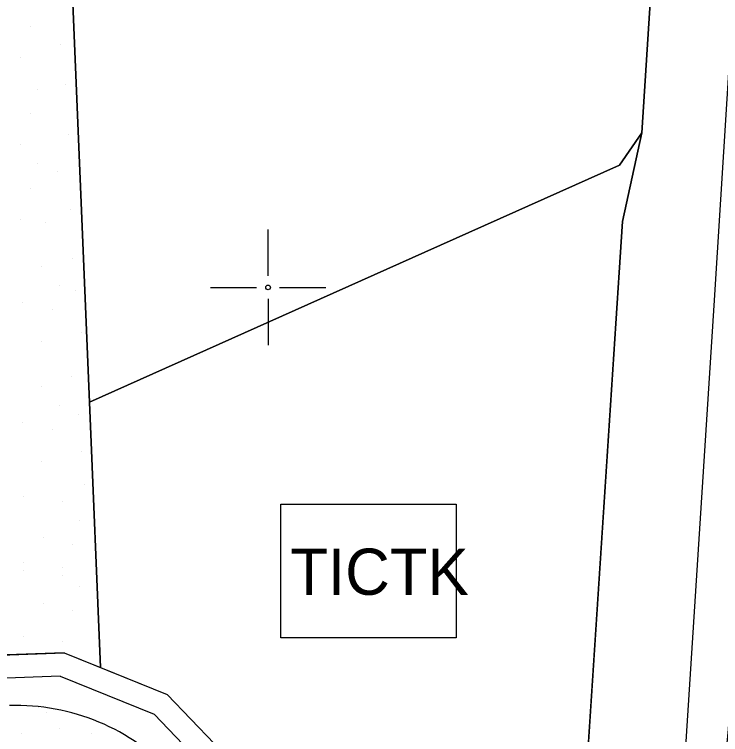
# Model space of a CAD drawing. Extents: x 419109 to 421295, y 4452223 to 4457798.
# Drawn here: x 419945.1 to 420098, y 4453403.2 to 4453559.1 of the extents above; entities that cross this region are included whole.
import ezdxf

# ---------------------------------------------------------------- set-up
doc = ezdxf.new("R2010")
doc.units = 0
for name, color, linetype in [('ADA', 7, 'Continuous'), ('ADAKENARI', 7, 'Continuous'), ('Default', 7, 'Continuous'), ('KALDIRIM', 7, 'Continuous'), ('LJ_SEMBOL', 7, 'Continuous'), ('PAFTALAMA', 7, 'Continuous'), ('PL_AYA_PARK_DINLENME', 7, 'Continuous'), ('PL_TURZM', 7, 'Continuous'), ('RAYLI_TOPLU_TAŞIMA_HATTI', 7, 'Continuous'), ('TR_PARKALANI', 7, 'Continuous'), ('TR_TİC_TURIZM_K', 7, 'Continuous'), ('TR_TİCT', 7, 'Continuous')]:
    doc.layers.add(name, color=color, linetype=linetype)

# ---------------------------------------------------------------- blocks, each defined once
blk = doc.blocks.new('POINT_DISPLAY')
at = {"layer": 'Default'}
blk.add_line((0, 0), (0, 0), dxfattribs=at)

msp = doc.modelspace()

# ---------------------------------------------------------------- linework, layer by layer
at = {"layer": 'ADA'}
msp.add_line((419963.74, 4453417.74), (419952.2, 4453694.42), dxfattribs=at)
at = {"layer": 'ADAKENARI'}
for p, q in [((420084.07, 4453583.1), (420080.95, 4453533.45)), ((420076.07, 4453526.42), (420080.95, 4453533.45)), ((420080.95, 4453533.45), (420076.74, 4453514.23)), ((420076.07, 4453526.42), (420033.97, 4453507.61)), ((420076.74, 4453514.23), (420065.91, 4453348.58)), ((420033.97, 4453507.61), (419961.35, 4453475.15)), ((419955.88, 4453420.93), (419903.4, 4453419.08)), ((419955.88, 4453420.93), (419978.18, 4453411.89)), ((419978.18, 4453411.89), (419988.41, 4453401.25))]:
    msp.add_line(p, q, dxfattribs=at)
msp.add_arc((419945.6, 4453363.53), 46, 42.5151, 92.0182, dxfattribs=at)
at = {"layer": 'KALDIRIM'}
for p, q in [((420100.06, 4453552.29), (420096.48, 4453496.11)), ((420096.48, 4453496.11), (420075.56, 4453167.83)), ((419954.99, 4453415.89), (419903.57, 4453414.08)), ((419954.99, 4453415.89), (419975.31, 4453407.66)), ((419975.31, 4453407.66), (419984.63, 4453397.97))]:
    msp.add_line(p, q, dxfattribs=at)
at = {"layer": 'LJ_SEMBOL'}
msp.add_lwpolyline([(420002.78, 4453453.1), (420040.72, 4453453.1), (420040.72, 4453424.16), (420002.78, 4453424.16)], close=True, dxfattribs=at)
at = {"layer": 'PAFTALAMA'}
for p, q in [((420000, 4453502.5), (420000, 4453512.5)), ((419987.5, 4453500), (419997.5, 4453500)), ((420002.5, 4453500), (420012.5, 4453500)), ((420000, 4453497.5), (420000, 4453487.5))]:
    msp.add_line(p, q, dxfattribs=at)
msp.add_circle((420000, 4453500), 0.5, dxfattribs=at)
at = {"layer": 'PL_AYA_PARK_DINLENME'}
msp.add_lwpolyline([(419961.35, 4453475.15), (419952.2, 4453694.42), (419939.23, 4453693.51), (419936.24, 4453693.29), (419939.48, 4453615.5), (419914.93, 4453613.25), (419917.11, 4453561.14), (419919.26, 4453509.4), (419938.37, 4453510.08), (419942.11, 4453420.44), (419955.88, 4453420.93), (419963.74, 4453417.74), (419961.35, 4453475.15)], dxfattribs=at)
msp.add_arc((419945.6, 4453363.53), 46, 42.5151, 92.0182, dxfattribs=at)
at = {"layer": 'PL_TURZM'}
for points in [[(419952.2, 4453694.42), (419961.35, 4453475.15), (420033.97, 4453507.61), (420076.07, 4453526.42), (420080.95, 4453533.45), (420084.07, 4453583.1)], [(419961.35, 4453475.15), (419963.74, 4453417.74), (419978.18, 4453411.89), (419988.41, 4453401.25), (419997.92, 4453389.08), (420007.85, 4453361.47), (420006.28, 4453340.53), (420065.42, 4453341.09), (420065.91, 4453348.58), (420076.74, 4453514.23), (420080.95, 4453533.45), (420076.07, 4453526.42), (420033.97, 4453507.61), (419961.35, 4453475.15)]]:
    msp.add_lwpolyline(points, dxfattribs=at)
at = {"layer": 'RAYLI_TOPLU_TAŞIMA_HATTI'}
msp.add_arc((425082.72, 4452994.01), 5000, 175.25584, 176.39423, dxfattribs=at)
at = {"layer": 'TR_TİC_TURIZM_K'}
for points in [[(420065.42, 4453341.09), (420065.91, 4453348.58), (420076.74, 4453514.23), (420080.95, 4453533.45), (420076.07, 4453526.42), (420033.97, 4453507.61), (419961.35, 4453475.15), (419963.74, 4453417.74), (419978.18, 4453411.89), (419988.41, 4453401.25), (419997.92, 4453389.08), (420007.85, 4453361.47), (420006.28, 4453340.53), (420065.42, 4453341.09)], [(420002.78, 4453424.16), (420002.78, 4453453.1), (420040.72, 4453453.1), (420040.72, 4453424.16), (420002.78, 4453424.16)]]:
    msp.add_lwpolyline(points, dxfattribs=at)
at = {"layer": 'TR_TİCT'}
msp.add_lwpolyline([(419952.2, 4453694.42), (419961.35, 4453475.15), (420033.97, 4453507.61), (420076.07, 4453526.42), (420080.95, 4453533.45), (420084.07, 4453583.1)], dxfattribs=at)

# ---------------------------------------------------------------- block references
at = {"layer": 'TR_PARKALANI', "xscale": 0.1, "yscale": 0.10000000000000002}
for p in [(419948.61, 4453556.43), (419955.07, 4453552.47), (419946.41, 4453549.68), (419950.13, 4453542.91), (419956.11, 4453543.88), (419948.61, 4453537.63), (419956.85, 4453533.08), (419946.41, 4453530.87), (419950.13, 4453526.74), (419954.48, 4453525.09), (419948.61, 4453521.46), (419957.29, 4453516.8), (419946.41, 4453514.7), (419951.82, 4453513.99), (419957.66, 4453506.22), (419951.02, 4453504.55), (419954.74, 4453500.42), (419958.25, 4453499.34), (419946.87, 4453496.69), (419953.22, 4453495.13), (419959.51, 4453490.31), (419951.02, 4453488.38), (419957.37, 4453480.7), (419951.02, 4453478.6), (419954.74, 4453474.47), (419958.99, 4453472.41), (419946.87, 4453470.74), (419953.22, 4453469.18), (419959.66, 4453464.56), (419951.02, 4453462.43), (419960.18, 4453457.31), (419947.1, 4453454.83), (419955.53, 4453453.78), (419959.25, 4453449.65), (419951.38, 4453445.92), (419957.73, 4453444.36), (419947.1, 4453440.53), (419947.1, 4453438.65), (419955.53, 4453439.49), (419955.53, 4453437.61), (419959.25, 4453435.36), (419951.38, 4453431.63), (419957.73, 4453430.07), (419947.1, 4453424.36), (419955.53, 4453423.32), (419950.3, 4453409.13), (419952.04, 4453408.01), (419954.91, 4453404.55), (419946.59, 4453403.42), (419961.82, 4453403.42)]:
    msp.add_blockref('POINT_DISPLAY', p, dxfattribs=at)

# ---------------------------------------------------------------- texts
at = {"layer": 'LJ_SEMBOL'}
msp.add_text('TICTK', height=10, dxfattribs=at).set_placement((420004.81, 4453433.48))

doc.saveas('drawing.dxf')
